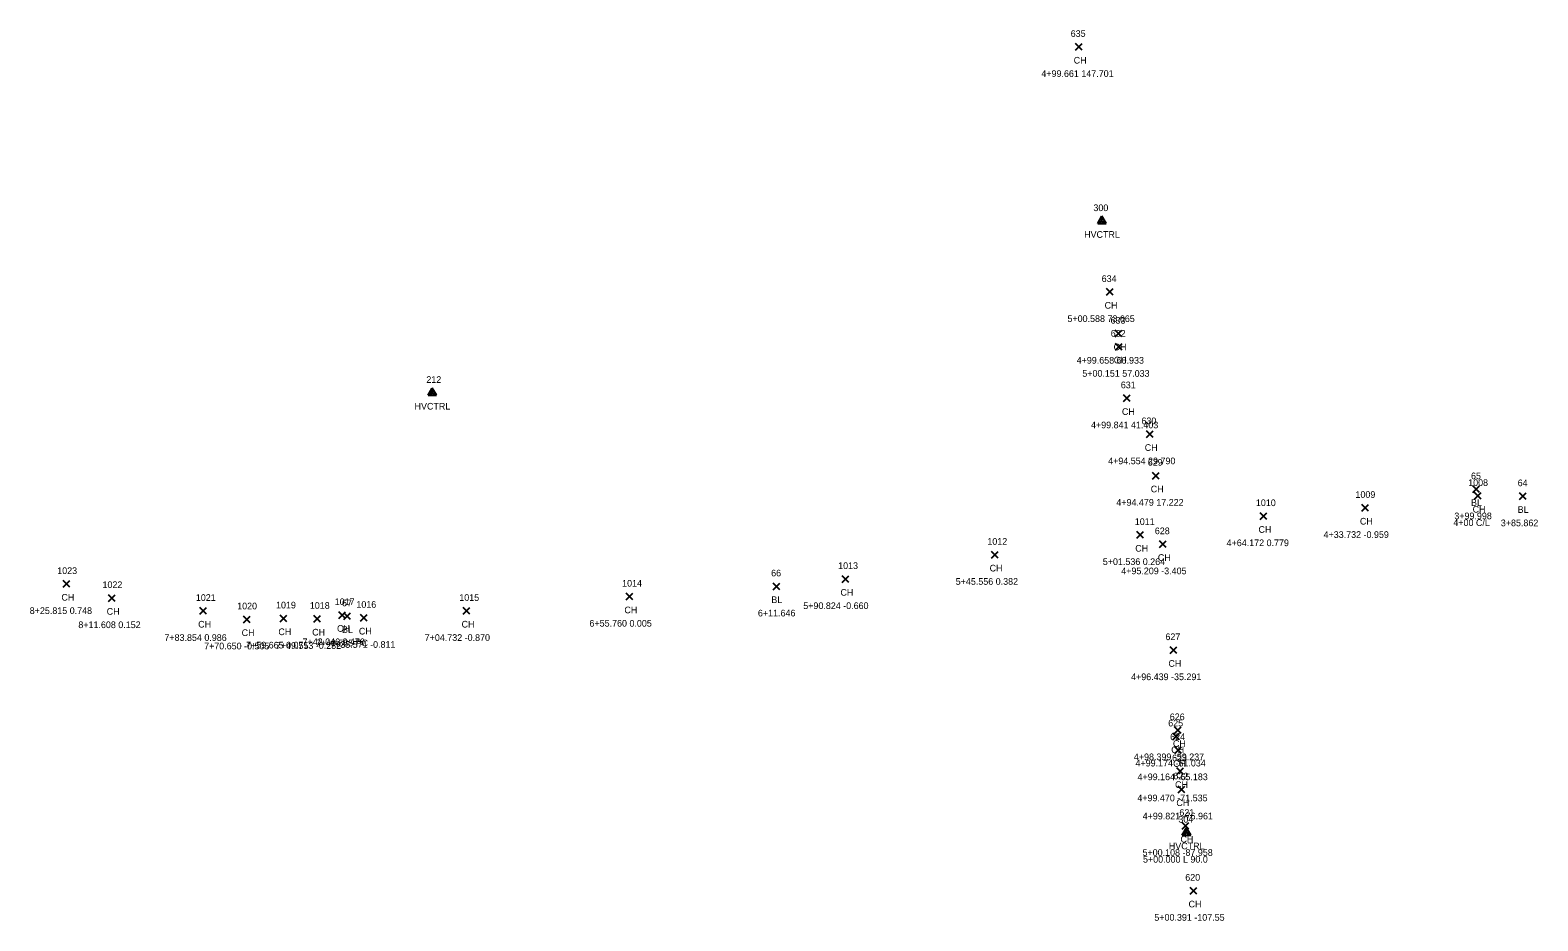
# Model space of a CAD drawing. Extents: x 89316 to 92454, y 84175 to 86051.
# Drawn here: x 91102.8 to 91554.5, y 84458.5 to 84725.5 of the extents above; entities that cross this region are included whole.
import ezdxf

# ---------------------------------------------------------------- set-up
doc = ezdxf.new("R2010")
doc.units = 0
for name, color, linetype in [('C_A', 7, 'Continuous'), ('C_C', 7, 'Continuous'), ('C_I', 7, 'Continuous'), ('C_TIC', 7, 'Continuous'), ('CPSM', 7, 'Continuous'), ('L_A', 7, 'Continuous'), ('L_C', 7, 'Continuous'), ('L_I', 7, 'Continuous'), ('L_TIC', 7, 'Continuous')]:
    doc.layers.add(name, color=color, linetype=linetype)

msp = doc.modelspace()

# ---------------------------------------------------------------- linework, layer by layer
at = {"layer": 'C_TIC'}
for points in [[(91535.04, 84586.85), (91537.04, 84588.85)], [(91537.04, 84586.85), (91535.04, 84588.85)], [(91549.02, 84584.76), (91551.02, 84586.76)], [(91551.02, 84584.76), (91549.02, 84586.76)], [(91325.4, 84557.72), (91327.4, 84559.72)], [(91327.4, 84557.72), (91325.4, 84559.72)], [(91196.77, 84548.77), (91198.77, 84550.77)], [(91198.77, 84548.77), (91196.77, 84550.77)]]:
    msp.add_lwpolyline(points, dxfattribs=at)
at = {"layer": 'CPSM'}
for p, q in [((91422.67, 84667.49), (91423.92, 84669.66)), ((91425.17, 84667.49), (91423.92, 84669.66)), ((91423.92, 84668.21), (91423.92, 84669.66)), ((91422.67, 84667.49), (91423.92, 84668.21)), ((91422.67, 84667.49), (91425.17, 84667.49)), ((91423.92, 84668.21), (91423.92, 84668.21)), ((91423.92, 84668.21), (91425.17, 84667.49)), ((91222.07, 84616.01), (91223.32, 84618.18)), ((91222.07, 84616.01), (91223.32, 84616.73)), ((91222.07, 84616.01), (91224.57, 84616.01)), ((91224.57, 84616.01), (91223.32, 84618.18)), ((91223.32, 84616.73), (91223.32, 84618.18)), ((91223.32, 84616.73), (91223.32, 84616.73)), ((91223.32, 84616.73), (91224.57, 84616.01)), ((91448.03, 84484.2), (91449.28, 84486.36)), ((91448.03, 84484.2), (91449.28, 84484.92)), ((91448.03, 84484.2), (91450.53, 84484.2)), ((91450.53, 84484.2), (91449.28, 84486.36)), ((91449.28, 84484.92), (91449.28, 84486.36)), ((91449.28, 84484.92), (91449.28, 84484.92)), ((91449.28, 84484.92), (91450.53, 84484.2))]:
    msp.add_line(p, q, dxfattribs=at)
at = {"layer": 'L_TIC'}
for points in [[(91415.99, 84719.43), (91417.99, 84721.43)], [(91417.99, 84719.43), (91415.99, 84721.43)], [(91425.27, 84645.97), (91427.27, 84647.97)], [(91427.27, 84645.97), (91425.27, 84647.97)], [(91427.94, 84633.49), (91429.94, 84635.49)], [(91429.94, 84633.49), (91427.94, 84635.49)], [(91427.99, 84629.56), (91429.99, 84631.56)], [(91429.99, 84629.56), (91427.99, 84631.56)], [(91430.45, 84614.12), (91432.45, 84616.12)], [(91432.45, 84614.12), (91430.45, 84616.12)], [(91437.28, 84603.34), (91439.28, 84605.34)], [(91439.28, 84603.34), (91437.28, 84605.34)], [(91439.08, 84590.91), (91441.08, 84592.91)], [(91441.08, 84590.91), (91439.08, 84592.91)], [(91535.52, 84584.83), (91537.52, 84586.83)], [(91537.52, 84584.83), (91535.52, 84586.83)], [(91471.37, 84578.79), (91473.37, 84580.79)], [(91473.37, 84578.79), (91471.37, 84580.79)], [(91501.76, 84581.26), (91503.76, 84583.26)], [(91503.76, 84581.26), (91501.76, 84583.26)], [(91434.43, 84573.14), (91436.43, 84575.14)], [(91436.43, 84573.14), (91434.43, 84575.14)], [(91441.2, 84570.37), (91443.2, 84572.37)], [(91443.2, 84570.37), (91441.2, 84572.37)], [(91390.81, 84567.2), (91392.81, 84569.2)], [(91392.81, 84567.2), (91390.81, 84569.2)], [(91346.12, 84559.93), (91348.12, 84561.93)], [(91348.12, 84559.93), (91346.12, 84561.93)], [(91112.72, 84558.45), (91114.72, 84560.45)], [(91114.72, 84558.45), (91112.72, 84560.45)], [(91126.27, 84554.22), (91128.27, 84556.22)], [(91128.27, 84554.22), (91126.27, 84556.22)], [(91281.4, 84554.66), (91283.4, 84556.66)], [(91283.4, 84554.66), (91281.4, 84556.66)], [(91153.68, 84550.38), (91155.68, 84552.38)], [(91155.68, 84550.38), (91153.68, 84552.38)], [(91232.6, 84550.39), (91234.6, 84552.39)], [(91234.6, 84550.39), (91232.6, 84552.39)], [(91166.71, 84547.84), (91168.71, 84549.84)], [(91168.71, 84547.84), (91166.71, 84549.84)], [(91177.71, 84548.12), (91179.71, 84550.12)], [(91179.71, 84548.12), (91177.71, 84550.12)], [(91187.83, 84548), (91189.83, 84550)], [(91189.83, 84548), (91187.83, 84550)], [(91195.28, 84549.12), (91197.28, 84551.12)], [(91197.28, 84549.12), (91195.28, 84551.12)], [(91201.83, 84548.31), (91203.83, 84550.31)], [(91203.83, 84548.31), (91201.83, 84550.31)], [(91444.37, 84538.62), (91446.37, 84540.62)], [(91446.37, 84538.62), (91444.37, 84540.62)], [(91445.73, 84514.63), (91447.73, 84516.63)], [(91447.73, 84514.63), (91445.73, 84516.63)], [(91445.2, 84512.75), (91447.2, 84514.75)], [(91447.2, 84512.75), (91445.2, 84514.75)], [(91445.79, 84508.64), (91447.79, 84510.64)], [(91447.79, 84508.64), (91445.79, 84510.64)], [(91446.36, 84502.31), (91448.36, 84504.31)], [(91448.36, 84502.31), (91446.36, 84504.31)], [(91446.76, 84496.88), (91448.76, 84498.88)], [(91448.76, 84496.88), (91446.76, 84498.88)], [(91447.99, 84485.95), (91449.99, 84487.95)], [(91449.99, 84485.95), (91447.99, 84487.95)], [(91450.4, 84466.5), (91452.4, 84468.5)], [(91452.4, 84466.5), (91450.4, 84468.5)]]:
    msp.add_lwpolyline(points, dxfattribs=at)

# ---------------------------------------------------------------- texts
at = {"layer": 'C_A'}
for s, p in [('HVCTRL', (91418.61, 84663.21)), ('HVCTRL', (91218.01, 84611.73)), ('BL', (91534.52, 84582.85)), ('BL', (91548.5, 84580.76)), ('BL', (91324.89, 84553.72)), ('BL', (91196.26, 84544.77)), ('HVCTRL', (91443.98, 84479.92))]:
    msp.add_text(s, height=2, dxfattribs=at).set_placement(p)
at = {"layer": 'C_C'}
for s, p in [('3+99.998', (91529.52, 84578.85)), ('3+85.862', (91543.45, 84576.76)), ('6+11.646', (91320.87, 84549.72)), ('7+40.585 PC', (91188.38, 84540.77)), ('5+00.000 L 90.0', (91436.25, 84475.92))]:
    msp.add_text(s, height=2, dxfattribs=at).set_placement(p)
at = {"layer": 'C_I'}
for s, p in [('300', (91421.39, 84671.21)), ('212', (91221.53, 84619.73)), ('65', (91534.52, 84590.85)), ('64', (91548.5, 84588.76)), ('66', (91324.84, 84561.72)), ('67', (91196.26, 84552.77)), ('304', (91446.84, 84487.92))]:
    msp.add_text(s, height=2, dxfattribs=at).set_placement(p)
at = {"layer": 'L_A'}
for p in [(91415.48, 84715.43), (91424.75, 84641.97), (91427.43, 84629.49), (91427.48, 84625.56), (91429.93, 84610.12), (91436.77, 84599.34), (91438.57, 84586.91), (91501.24, 84577.26), (91535.01, 84580.83), (91470.85, 84574.79), (91433.92, 84569.14), (91440.69, 84566.37), (91390.3, 84563.2), (91112.21, 84554.45), (91345.61, 84555.93), (91125.76, 84550.22), (91280.88, 84550.66), (91153.17, 84546.38), (91232.09, 84546.39), (91166.2, 84543.84), (91177.2, 84544.12), (91187.32, 84544), (91194.77, 84545.12), (91201.32, 84544.31), (91443.86, 84534.62), (91445.21, 84510.63), (91444.69, 84508.75), (91445.27, 84504.64), (91445.85, 84498.31), (91446.24, 84492.88), (91447.47, 84481.95), (91449.89, 84462.5)]:
    msp.add_text('CH', height=2, dxfattribs=at).set_placement(p)
at = {"layer": 'L_C'}
for s, p in [('4+99.661 147.701', (91405.8, 84711.43)), ('5+00.588 73.665', (91413.62, 84637.97)), ('4+99.658 60.933', (91416.37, 84625.49)), ('5+00.151 57.033', (91418.06, 84621.56)), ('4+99.841 41.403', (91420.67, 84606.12)), ('4+94.554 29.790', (91425.8, 84595.34)), ('4+94.479 17.222', (91428.26, 84582.91)), ('4+00 C/L', (91529.23, 84576.83)), ('4+33.732 -0.959', (91490.35, 84573.26)), ('4+64.172 0.779', (91461.3, 84570.79)), ('5+01.536 0.264', (91424.2, 84565.14)), ('5+45.556 0.382', (91380.14, 84559.2)), ('4+95.209 -3.405', (91429.73, 84562.37)), ('8+25.815 0.748', (91102.71, 84550.45)), ('5+90.824 -0.660', (91334.46, 84551.93)), ('8+11.608 0.152', (91117.27, 84546.22)), ('6+55.760 0.005', (91270.41, 84546.66)), ('7+83.854 0.986', (91143.05, 84542.38)), ('7+42.046 0.470', (91184.45, 84541.12)), ('7+04.732 -0.870', (91221.04, 84542.39)), ('7+70.650 -0.505', (91154.95, 84539.84)), ('7+59.665 0.071', (91167.53, 84540.12)), ('7+49.553 -0.232', (91176.44, 84540)), ('7+35.571 -0.811', (91192.71, 84540.31)), ('4+96.439 -35.291', (91432.68, 84530.62)), ('4+98.399 -59.237', (91433.51, 84506.63)), ('4+99.174 -61.034', (91434, 84504.75)), ('4+99.164 -65.183', (91434.61, 84500.64)), ('4+99.470 -71.535', (91434.55, 84494.31)), ('4+99.821 -76.961', (91436.15, 84488.88)), ('5+00.108 -87.958', (91436.1, 84477.95)), ('5+00.391 -107.55', (91439.65, 84458.5))]:
    msp.add_text(s, height=2, dxfattribs=at).set_placement(p)
at = {"layer": 'L_I'}
for s, p in [('635', (91414.58, 84723.43)), ('634', (91423.86, 84649.97)), ('633', (91426.53, 84637.49)), ('632', (91426.58, 84633.56)), ('631', (91429.6, 84618.12)), ('630', (91435.78, 84607.34)), ('629', (91437.67, 84594.91)), ('1008', (91533.67, 84588.83)), ('1010', (91470.07, 84582.79)), ('1009', (91499.9, 84585.26)), ('1011', (91433.79, 84577.14)), ('628', (91439.79, 84574.37)), ('1012', (91389.61, 84571.2)), ('1013', (91344.91, 84563.93)), ('1023', (91110.95, 84562.45)), ('1022', (91124.5, 84558.22)), ('1021', (91152.48, 84554.38)), ('1015', (91231.4, 84554.39)), ('1014', (91280.19, 84558.66)), ('1020', (91164.85, 84551.84)), ('1019', (91176.5, 84552.12)), ('1018', (91186.63, 84552)), ('1017', (91194.08, 84553.12)), ('1016', (91200.57, 84552.31)), ('627', (91442.96, 84542.62)), ('626', (91444.26, 84518.63)), ('625', (91443.8, 84516.75)), ('624', (91444.38, 84512.64)), ('623', (91444.95, 84506.31)), ('622', (91445.35, 84500.88)), ('621', (91447.14, 84489.95)), ('620', (91448.91, 84470.5))]:
    msp.add_text(s, height=2, dxfattribs=at).set_placement(p)

doc.saveas('drawing.dxf')
